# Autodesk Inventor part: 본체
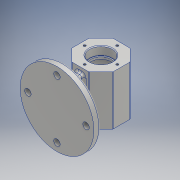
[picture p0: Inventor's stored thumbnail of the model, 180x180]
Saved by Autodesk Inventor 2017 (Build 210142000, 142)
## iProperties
Part Number: 본체
Material: 알루미늄 6061
Document SubType Name: Modeling
Designer: 00-00
Density: 2.7 g/cm^3
Appearance: 알루미늄 - 평지
Mass: 557.122 g
Surface Area: 509.668 cm^2
Volume: 206.342 cm^3
Author: 00-00
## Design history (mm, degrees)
sketch "스케치1"
  geometry: C1 r 52 at (0, 0); 1 further point
  constraints: 1 centre point, 1 coincident
  dimensions: "d0" = 104 diameter of C1
extrude "돌출1" new body sketch "스케치1" distance "d3" = 10; taper "d4" = 0 deg
sketch "스케치2" dims "d5" = 58
  geometry: L1 (-29, 74.012)-(-12.012, 91); L2 (-12.012, 91)-(12.012, 91); L3 (12.012, 91)-(29, 74.012); L4 (29, 74.012)-(29, 49.988); L5 (29, 49.988)-(12.012, 33); L6 (12.012, 33)-(-12.012, 33); L7 (-12.012, 33)-(-29, 49.988); L8 (-29, 49.988)-(-29, 74.012); L9 (-52, 0)-(52, 0) reference; 5 further points
  constraints: 16 end point, 2 midpoint, 1 coincident, 1 horizontal alignment, 1 vertical, 1 vertical alignment, 19 other
  dimensions: "d6" = 62 distance from line of L9 point (0, 62)
extrude "돌출2" join sketch "스케치2" stored distance "d7" = 70; taper "d8" = 0 deg
sketch "스케치3"
  geometry: L1 (62, 52.005)-(62, -52.005); L2 (91, 35)-(74.012, 35) reference; L3 (78, 35)-(78, 23); L4 (78, 23)-(76, 23); L5 (76, 23)-(76, 20); L6 (76, 20)-(84, 20); L7 (84, 20)-(84, -20); L8 (84, -20)-(76, -20); L9 (76, -20)-(76, -23); L10 (76, -23)-(78, -23); L11 (78, -23)-(78, -35); L12 (74.012, -35)-(91, -35) reference; L13 (78, 35)-(62, 35); L14 (74.012, 35)-(49.988, 35) reference; L15 (78, -35)-(62, -35); L16 (49.988, -35)-(74.012, -35) reference; L17 (62, 35)-(62, -35); 3 further points
  constraints: 26 end point, 6 perpendicular, 6 point on line, 4 midpoint, 2 vertical, 1 collinear, 1 horizontal alignment
  dimensions: "d9" = 62 horizontal distance of point (0, 0) L1.end; "d10" = 44 diameter of L7 L1; "d11" = 32 diameter of L3 L1; "d12" = 28 diameter of L5 L1; "d13" = 40 distance of L6.end L7.end; "d14" = 12 distance of L3.start L3.end; "d15" = 12 distance of L10.end L11.end; "d16" = 3 distance of L8.end L9.end
revolve "회전1" sketch "스케치3" stored, may be unused: angle "d17" = 90 deg
sketch "스케치4"
  geometry: L1 (-5, -28)-(5, -28); L2 (5, -28)-(5, 28); L3 (5, 28)-(-5, 28); L4 (-5, 28)-(-5, -28); 3 further points
  constraints: 8 end point, 2 midpoint, 2 perpendicular, 1 horizontal, 1 horizontal alignment, 1 vertical alignment
  dimensions: "d18" = 10 distance of L1.start L1.end; "d19" = 56 distance of L1.end L2.end; "d20" = 10 distance of L2.end L3.end; "d21" = 56 distance of L3.end L1.start (derived)
extrude "돌출3" join sketch "스케치4" stored distance "d22" = 70; taper "d23" = 0 deg
fillet "모깎기1" dims "d24" = 3
fillet "모깎기2" dims "d25" = 3
sketch "스케치5"
  geometry: L1 (29, 74.012)-(12.012, 91) reference; L2 (12.012, 91)-(-12.012, 91) reference; L3 (-12.012, 91)-(-29, 74.012) reference; L4 (-29, 74.012)-(-29, 49.988) reference; L5 (-29, 49.988)-(-12.012, 33) reference; L6 (-12.012, 33)-(12.012, 33) reference; L7 (12.012, 33)-(29, 49.988) reference; L8 (29, 49.988)-(29, 74.012) reference; C1 r 16 at (0, 62) reference; 5 further points
  constraints: 1 vertical alignment, 5 other
  dimensions: "d28" = 360 deg dimension on C1.centre point (0, 85) (derived); "d30" = 23 distance of C1.centre point (0, 85)
hole "구멍1" sketch "스케치5" at (0, 85), (-23, 62), (0, 39), (23, 62) diameter "d31" = 3.242; stored, may be unused: countersink angle "d35" = 90 deg, drill point angle "d37" = 118 deg; dims "d32" = 8, "d33" = 4, "d34" = 2, "d36" = 10
sketch "스케치6"
  geometry: L1 (0, 0)-(-24.024, 0) reference; L2 (-41.012, 70)-(-41.012, 0) reference; C1 r 10 at (-12.012, 35); 1 further point
  constraints: 1 centre point
  dimensions: "d38" = 20 diameter of C1; "d39" = 35 distance from line of L1 C1.centre; "d40" = 29 distance from line of L2 C1.centre
extrude "돌출4" join sketch "스케치6" distance "d41" = 5; taper "d42" = 0 deg
sketch "스케치7"
  geometry: C1 r 10 at (0, 0) reference; 1 further point
hole "구멍2" sketch "스케치7" at (0, 0) diameter "d43" = 10.106; stored, may be unused: countersink angle "d47" = 90 deg, drill point angle "d49" = 118 deg; dims "d44" = 50, "d45" = 16, "d46" = 2, "d48" = 50
sketch "스케치8"
  geometry: 5 further points
  constraints: 2 horizontal alignment, 5 other
  dimensions: "d52" = 360 deg dimension on point (0, 0) point (41, 0) (derived); "d54" = 41 distance of point (0, 0) point (41, 0)
hole "구멍3" sketch "스케치8" at (41, 0), (0, 41), (-41, 0), (0, -41) diameter "d55" = 9; stored, may be unused: countersink angle "d59" = 90 deg, drill point angle "d61" = 118 deg; dims "d56" = 50, "d57" = 16, "d58" = 2, "d60" = 50
sketch "스케치9"
  geometry: L1 (24.024, 70)-(41.012, 70) reference; 2 further points
  constraints: 1 other
  dimensions: "d62" = 35 distance from line of L1 point (11.776, 35)
feature "엠보싱1" sketch "스케치9" dims "d63" = 0.5, "d64" = 0
chamfer "모따기1" distance "d65" = 1; stored, may be unused: second distance "d66" = 2, angle "d67" = 45 deg
chamfer "모따기2" distance "d68" = 1; stored, may be unused: second distance "d69" = 2, angle "d70" = 45 deg
fillet "모깎기3" dims "d71" = 0.3
fillet "모깎기4" dims "d72" = 3
fillet "모깎기5" dims "d73" = 3
fillet "모깎기6" dims "d74" = 1
fillet "모깎기7" dims "d75" = 1
node "솔리드1"
mirror "미러1"
node "투영된 루프1"
node "투영된 루프2"
